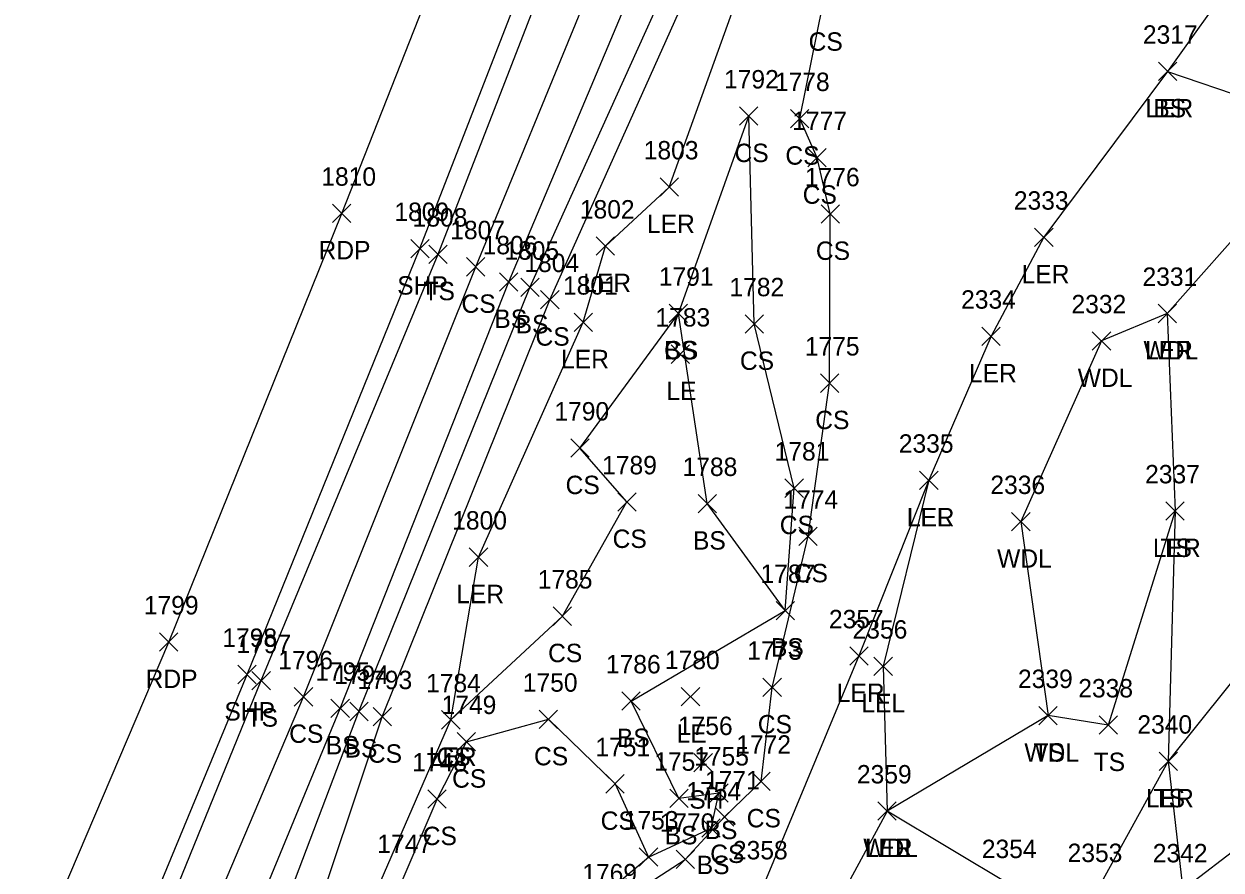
# Model space of a CAD drawing. Extents: x 1483143 to 1488182, y 802902 to 807581.
# Drawn here: x 1487782.5 to 1487912.6, y 806312.7 to 806404.6 of the extents above; entities that cross this region are included whole.
import ezdxf

# ---------------------------------------------------------------- set-up
doc = ezdxf.new("R2010")
doc.units = 0
for name, color, linetype in [('L_A', 7, 'Continuous'), ('L_I', 7, 'Continuous'), ('L_TIC', 7, 'Continuous'), ('LARO', 7, 'Continuous'), ('LAWA', 7, 'Continuous'), ('LELB', 7, 'Continuous'), ('P_A', 7, 'Continuous'), ('P_I', 7, 'Continuous'), ('P_TIC', 7, 'Continuous'), ('PET', 7, 'Continuous'), ('PSP', 7, 'Continuous')]:
    doc.layers.add(name, color=color, linetype=linetype)

msp = doc.modelspace()

# ---------------------------------------------------------------- linework, layer by layer
at = {"layer": 'L_TIC'}
for points in [[(1487905.78, 806398.47), (1487907.78, 806400.47)], [(1487907.78, 806398.47), (1487905.78, 806400.47)], [(1487905.78, 806398.47), (1487907.78, 806400.47)], [(1487907.78, 806398.47), (1487905.78, 806400.47)], [(1487860.27, 806393.61), (1487862.27, 806395.61)], [(1487862.27, 806393.61), (1487860.27, 806395.61)], [(1487860.27, 806393.61), (1487862.27, 806395.61)], [(1487862.27, 806393.61), (1487860.27, 806395.61)], [(1487865.81, 806393.33), (1487867.81, 806395.33)], [(1487867.81, 806393.33), (1487865.81, 806395.33)], [(1487867.69, 806389.08), (1487869.69, 806391.08)], [(1487869.69, 806389.08), (1487867.69, 806391.08)], [(1487851.63, 806385.9), (1487853.63, 806387.9)], [(1487853.63, 806385.9), (1487851.63, 806387.9)], [(1487869.12, 806382.98), (1487871.12, 806384.98)], [(1487871.12, 806382.98), (1487869.12, 806384.98)], [(1487892.33, 806380.44), (1487894.33, 806382.44)], [(1487894.33, 806380.44), (1487892.33, 806382.44)], [(1487826.52, 806378.6), (1487828.52, 806380.6)], [(1487828.52, 806378.6), (1487826.52, 806380.6)], [(1487844.69, 806379.48), (1487846.69, 806381.48)], [(1487846.69, 806379.48), (1487844.69, 806381.48)], [(1487830.61, 806377.23), (1487832.61, 806379.23)], [(1487832.61, 806377.23), (1487830.61, 806379.23)], [(1487834.19, 806375.59), (1487836.19, 806377.59)], [(1487836.19, 806375.59), (1487834.19, 806377.59)], [(1487836.5, 806375), (1487838.5, 806377)], [(1487838.5, 806375), (1487836.5, 806377)], [(1487838.66, 806373.66), (1487840.66, 806375.66)], [(1487840.66, 806373.66), (1487838.66, 806375.66)], [(1487852.63, 806372.17), (1487854.63, 806374.17)], [(1487854.63, 806372.17), (1487852.63, 806374.17)], [(1487852.63, 806372.17), (1487854.63, 806374.17)], [(1487854.63, 806372.17), (1487852.63, 806374.17)], [(1487905.74, 806372.16), (1487907.74, 806374.16)], [(1487907.74, 806372.16), (1487905.74, 806374.16)], [(1487905.74, 806372.16), (1487907.74, 806374.16)], [(1487907.74, 806372.16), (1487905.74, 806374.16)], [(1487842.29, 806371.21), (1487844.29, 806373.21)], [(1487844.29, 806371.21), (1487842.29, 806373.21)], [(1487860.87, 806371.03), (1487862.87, 806373.03)], [(1487862.87, 806371.03), (1487860.87, 806373.03)], [(1487886.6, 806369.68), (1487888.6, 806371.68)], [(1487888.6, 806369.68), (1487886.6, 806371.68)], [(1487898.59, 806369.18), (1487900.59, 806371.18)], [(1487900.59, 806369.18), (1487898.59, 806371.18)], [(1487852.83, 806367.74), (1487854.83, 806369.74)], [(1487854.83, 806367.74), (1487852.83, 806369.74)], [(1487869.05, 806364.59), (1487871.05, 806366.59)], [(1487871.05, 806364.59), (1487869.05, 806366.59)], [(1487841.93, 806357.53), (1487843.93, 806359.53)], [(1487843.93, 806357.53), (1487841.93, 806359.53)], [(1487879.83, 806354.03), (1487881.83, 806356.03)], [(1487881.83, 806354.03), (1487879.83, 806356.03)], [(1487879.83, 806354.03), (1487881.83, 806356.03)], [(1487881.83, 806354.03), (1487879.83, 806356.03)], [(1487865.2, 806353.18), (1487867.2, 806355.18)], [(1487867.2, 806353.18), (1487865.2, 806355.18)], [(1487847.04, 806351.68), (1487849.04, 806353.68)], [(1487849.04, 806351.68), (1487847.04, 806353.68)], [(1487855.77, 806351.5), (1487857.77, 806353.5)], [(1487857.77, 806351.5), (1487855.77, 806353.5)], [(1487906.59, 806350.7), (1487908.59, 806352.7)], [(1487908.59, 806350.7), (1487906.59, 806352.7)], [(1487906.59, 806350.7), (1487908.59, 806352.7)], [(1487908.59, 806350.7), (1487906.59, 806352.7)], [(1487889.83, 806349.54), (1487891.83, 806351.54)], [(1487891.83, 806349.54), (1487889.83, 806351.54)], [(1487866.72, 806347.95), (1487868.72, 806349.95)], [(1487868.72, 806347.95), (1487866.72, 806349.95)], [(1487830.91, 806345.68), (1487832.91, 806347.68)], [(1487832.91, 806345.68), (1487830.91, 806347.68)], [(1487864.24, 806339.88), (1487866.24, 806341.88)], [(1487866.24, 806339.88), (1487864.24, 806341.88)], [(1487840.03, 806339.27), (1487842.03, 806341.27)], [(1487842.03, 806339.27), (1487840.03, 806341.27)], [(1487872.24, 806334.95), (1487874.24, 806336.95)], [(1487874.24, 806334.95), (1487872.24, 806336.95)], [(1487874.87, 806333.83), (1487876.87, 806335.83)], [(1487876.87, 806333.83), (1487874.87, 806335.83)], [(1487807.3, 806332.26), (1487809.3, 806334.26)], [(1487809.3, 806332.26), (1487807.3, 806334.26)], [(1487811.9, 806330.5), (1487813.9, 806332.5)], [(1487813.9, 806330.5), (1487811.9, 806332.5)], [(1487853.94, 806330.51), (1487855.94, 806332.51)], [(1487855.94, 806330.51), (1487853.94, 806332.51)], [(1487862.81, 806331.53), (1487864.81, 806333.53)], [(1487864.81, 806331.53), (1487862.81, 806333.53)], [(1487815.88, 806329.25), (1487817.88, 806331.25)], [(1487817.88, 806329.25), (1487815.88, 806331.25)], [(1487847.49, 806330.05), (1487849.49, 806332.05)], [(1487849.49, 806330.05), (1487847.49, 806332.05)], [(1487817.92, 806328.91), (1487819.92, 806330.91)], [(1487819.92, 806328.91), (1487817.92, 806330.91)], [(1487820.45, 806328.34), (1487822.45, 806330.34)], [(1487822.45, 806328.34), (1487820.45, 806330.34)], [(1487827.9, 806328), (1487829.9, 806330)], [(1487829.9, 806328), (1487827.9, 806330)], [(1487827.9, 806328), (1487829.9, 806330)], [(1487829.9, 806328), (1487827.9, 806330)], [(1487838.5, 806328.06), (1487840.5, 806330.06)], [(1487840.5, 806328.06), (1487838.5, 806330.06)], [(1487892.79, 806328.46), (1487894.79, 806330.46)], [(1487894.79, 806328.46), (1487892.79, 806330.46)], [(1487892.79, 806328.46), (1487894.79, 806330.46)], [(1487894.79, 806328.46), (1487892.79, 806330.46)], [(1487899.33, 806327.44), (1487901.33, 806329.44)], [(1487901.33, 806327.44), (1487899.33, 806329.44)], [(1487829.6, 806325.63), (1487831.6, 806327.63)], [(1487831.6, 806325.63), (1487829.6, 806327.63)], [(1487855.32, 806323.35), (1487857.32, 806325.35)], [(1487857.32, 806323.35), (1487855.32, 806325.35)], [(1487905.84, 806323.5), (1487907.84, 806325.5)], [(1487907.84, 806323.5), (1487905.84, 806325.5)], [(1487905.84, 806323.5), (1487907.84, 806325.5)], [(1487907.84, 806323.5), (1487905.84, 806325.5)], [(1487861.61, 806321.32), (1487863.61, 806323.32)], [(1487863.61, 806321.32), (1487861.61, 806323.32)], [(1487845.74, 806321.05), (1487847.74, 806323.05)], [(1487847.74, 806321.05), (1487845.74, 806323.05)], [(1487857.03, 806320.04), (1487859.03, 806322.04)], [(1487859.03, 806320.04), (1487857.03, 806322.04)], [(1487826.41, 806319.39), (1487828.41, 806321.39)], [(1487828.41, 806319.39), (1487826.41, 806321.39)], [(1487852.69, 806319.47), (1487854.69, 806321.47)], [(1487854.69, 806319.47), (1487852.69, 806321.47)], [(1487857.64, 806317.45), (1487859.64, 806319.45)], [(1487859.64, 806317.45), (1487857.64, 806319.45)], [(1487875.29, 806318.09), (1487877.29, 806320.09)], [(1487877.29, 806318.09), (1487875.29, 806320.09)], [(1487875.29, 806318.09), (1487877.29, 806320.09)], [(1487877.29, 806318.09), (1487875.29, 806320.09)], [(1487875.29, 806318.09), (1487877.29, 806320.09)], [(1487877.29, 806318.09), (1487875.29, 806320.09)], [(1487856.18, 806316.24), (1487858.18, 806318.24)], [(1487858.18, 806316.24), (1487856.18, 806318.24)], [(1487849.38, 806313.09), (1487851.38, 806315.09)], [(1487851.38, 806313.09), (1487849.38, 806315.09)], [(1487849.38, 806313.09), (1487851.38, 806315.09)], [(1487851.38, 806313.09), (1487849.38, 806315.09)], [(1487853.37, 806312.84), (1487855.37, 806314.84)], [(1487855.37, 806312.84), (1487853.37, 806314.84)]]:
    msp.add_lwpolyline(points, dxfattribs=at)
at = {"layer": 'LARO'}
for points in [[(1487666.95, 805964.97), (1487680.31, 805984.75), (1487702.99, 806037.2), (1487715.7, 806058.03), (1487734.3, 806108.53), (1487742.02, 806134.63), (1487761.66, 806177.53), (1487786.65, 806227.9), (1487808.03, 806277.33), (1487813.76, 806294.17), (1487828.9, 806329), (1487831.91, 806346.68), (1487843.29, 806372.21), (1487845.69, 806380.48), (1487852.63, 806386.9), (1487863.18, 806416.3)], [(1487938.33, 806405.75), (1487927.08, 806402.62), (1487919.67, 806403.09), (1487914.11, 806409.79), (1487906.78, 806399.47), (1487893.33, 806381.44), (1487887.6, 806370.68), (1487880.83, 806355.03), (1487873.24, 806335.95), (1487862.81, 806310.84), (1487845.31, 806291.53), (1487837.06, 806275.13), (1487830.31, 806264.75), (1487822.51, 806259.14), (1487820.37, 806244.37)], [(1487906.74, 806373.16), (1487907.59, 806351.7), (1487906.84, 806324.5), (1487899.17, 806310.55), (1487889.85, 806310.98), (1487876.29, 806319.09)], [(1487880.83, 806355.03), (1487875.87, 806334.83), (1487876.29, 806319.09)]]:
    msp.add_lwpolyline(points, dxfattribs=at)
at = {"layer": 'LAWA'}
msp.add_lwpolyline([(1487942.37, 806424.18), (1487942.13, 806400.96), (1487924.66, 806393.36), (1487906.74, 806373.16), (1487899.59, 806370.18), (1487890.83, 806350.54), (1487893.79, 806329.46), (1487876.29, 806319.09), (1487863.09, 806294.65), (1487840.52, 806269.33), (1487843.55, 806264.22), (1487833.59, 806259.9), (1487830.72, 806250.51), (1487828.92, 806235.37), (1487823.44, 806218.85), (1487816.5, 806198.3), (1487812.31, 806191.59), (1487811.73, 806182.07)], dxfattribs=at)
at = {"layer": 'LELB'}
for points in [[(1487959.91, 806445.22), (1487960.75, 806398.74), (1487951.5, 806373.39), (1487932.63, 806356.69), (1487906.84, 806324.5), (1487908.42, 806310.52), (1487916.06, 806290.13), (1487905.83, 806276.22)], [(1487406.66, 805485.41), (1487431.45, 805531.24), (1487454.84, 805575.74), (1487473.75, 805612.05), (1487489.43, 805642.37), (1487507.64, 805678.53), (1487524.82, 805711.39), (1487541.86, 805746.09), (1487557.67, 805776.44), (1487575.49, 805812.01), (1487597.52, 805857.93), (1487620.62, 805906.82), (1487641.85, 805951.94), (1487662.18, 805996.35), (1487684.09, 806043.93), (1487694.42, 806066.95), (1487726.58, 806140.7), (1487745.85, 806185.55), (1487769.04, 806237.65), (1487788.58, 806284.85), (1487808.3, 806333.26), (1487827.52, 806379.6), (1487850.09, 806437.73)], [(1487410.04, 805483.24), (1487436.07, 805529.53), (1487459.78, 805575.03), (1487477.42, 805609.67), (1487492.45, 805639.09), (1487509.86, 805677.27), (1487528.68, 805708.85), (1487545.3, 805744.17), (1487561.79, 805774.32), (1487579.7, 805810.21), (1487602.04, 805856.31), (1487624.97, 805905.57), (1487645.72, 805950.02), (1487667.21, 805993.1), (1487687.16, 806043.23), (1487699.2, 806065.16), (1487730.65, 806138.87), (1487749.96, 806183.58), (1487772.93, 806235.17), (1487792.36, 806283.08), (1487812.9, 806331.5), (1487831.61, 806378.23), (1487855.61, 806436.65)], [(1487413.83, 805481.53), (1487440.22, 805526.89), (1487464.36, 805572.85), (1487481.71, 805606.55), (1487496.63, 805636.25), (1487514.9, 805673.97), (1487535.8, 805705.94), (1487549.07, 805741.59), (1487566.17, 805772.22), (1487583.99, 805807.69), (1487605.26, 805855.28), (1487629.33, 805903.01), (1487650.26, 805948.76), (1487670.48, 805991.25), (1487690.28, 806041.74), (1487702.22, 806061.37), (1487704.47, 806066.39), (1487735.28, 806136.71), (1487754, 806182.42), (1487776.55, 806233.47), (1487796.75, 806281.41), (1487816.88, 806330.25), (1487835.19, 806376.59), (1487859.78, 806434.97)], [(1487417, 805480.8), (1487442.28, 805525.8), (1487466.47, 805571.82), (1487483.84, 805604.86), (1487498.25, 805635.76), (1487518.24, 805671.86), (1487538.47, 805704.77), (1487552.2, 805739.67), (1487568.17, 805771.84), (1487585.97, 805806.76), (1487609.39, 805853.47), (1487632.34, 805900.81), (1487653.02, 805947.32), (1487672.59, 805990.01), (1487694.92, 806039.27), (1487707.45, 806059.25), (1487710.05, 806064.3), (1487737.97, 806135.43), (1487757.4, 806181.42), (1487778.76, 806231.94), (1487799.97, 806279.97), (1487818.92, 806329.91), (1487837.5, 806376), (1487863.45, 806433.38)], [(1487539.8, 805706.7), (1487554.99, 805738.51), (1487564.78, 805761.24), (1487572.42, 805770.06), (1487590.42, 805804.18), (1487613.31, 805851.36), (1487639.64, 805896.3), (1487657.07, 805945.9), (1487666.95, 805964.97), (1487675.89, 805987.99), (1487698.82, 806037.9), (1487713.56, 806059.8), (1487740.03, 806134.78), (1487759.8, 806179.98), (1487782.43, 806230.23), (1487804.48, 806278.55), (1487821.45, 806329.34), (1487839.66, 806374.66), (1487865.87, 806433.14)], [(1487966.07, 806415.18), (1487969.53, 806392.86), (1487952.94, 806357.28), (1487940.19, 806330.57), (1487921.69, 806320.66), (1487908.42, 806310.52), (1487904.09, 806299.8)], [(1487808.19, 806250.46), (1487814.65, 806254.45), (1487814.39, 806266.92), (1487820, 806278.4), (1487824.56, 806290.24), (1487835.69, 806296.25), (1487844.38, 806305.06), (1487845.93, 806308.34), (1487854.37, 806313.84), (1487858.64, 806318.45), (1487862.61, 806322.32), (1487863.81, 806332.53), (1487867.72, 806348.95), (1487870.05, 806365.59), (1487870.12, 806383.98), (1487868.69, 806390.08), (1487866.81, 806394.33), (1487869.32, 806406.71)], [(1487906.78, 806399.47), (1487924.66, 806393.36), (1487936.78, 806386.95), (1487951.5, 806373.39)], [(1487828.9, 806329), (1487841.03, 806340.27), (1487848.04, 806352.68), (1487842.93, 806358.53), (1487853.63, 806373.17), (1487861.27, 806394.61)], [(1487866.2, 806354.18), (1487861.87, 806372.03), (1487861.27, 806394.61)], [(1487813.76, 806294.17), (1487825.31, 806298.15), (1487840.36, 806305.67), (1487850.38, 806314.09), (1487857.18, 806317.24), (1487858.03, 806321.04), (1487853.69, 806320.47), (1487848.49, 806331.05), (1487865.24, 806340.88), (1487856.77, 806352.5), (1487853.63, 806373.17)], [(1487865.24, 806340.88), (1487866.2, 806354.18)], [(1487907.59, 806351.7), (1487900.33, 806328.44), (1487893.79, 806329.46)], [(1487825.31, 806298.15), (1487829.95, 806304.22), (1487823.6, 806311.52), (1487827.41, 806320.39), (1487830.6, 806326.63), (1487839.5, 806329.06), (1487846.74, 806322.05), (1487850.38, 806314.09)]]:
    msp.add_lwpolyline(points, dxfattribs=at)
at = {"layer": 'P_TIC'}
for points in [[(1487816.05, 806383.04), (1487818.05, 806385.04)], [(1487818.05, 806383.04), (1487816.05, 806385.04)], [(1487824.55, 806379.21), (1487826.55, 806381.21)], [(1487826.55, 806379.21), (1487824.55, 806381.21)], [(1487797.25, 806336.46), (1487799.25, 806338.46)], [(1487799.25, 806336.46), (1487797.25, 806338.46)], [(1487805.77, 806332.93), (1487807.77, 806334.93)], [(1487807.77, 806332.93), (1487805.77, 806334.93)]]:
    msp.add_lwpolyline(points, dxfattribs=at)
at = {"layer": 'PET'}
msp.add_lwpolyline([(1487396.33, 805490.41), (1487421.9, 805537.94), (1487444.13, 805580.16), (1487464.29, 805618.83), (1487479.8, 805648.39), (1487498.08, 805684.27), (1487514.57, 805717.15), (1487530.55, 805749.06), (1487547.16, 805782.47), (1487564.33, 805817.54), (1487585.71, 805863.32), (1487608.89, 805911.38), (1487630.35, 805956.68), (1487651.22, 806001.25), (1487672.63, 806048.33), (1487683.65, 806072.29), (1487715.61, 806144.47), (1487735.35, 806190.47), (1487757.48, 806241.03), (1487777.65, 806289.15), (1487798.25, 806337.46), (1487817.05, 806384.04), (1487839.67, 806441.4)], dxfattribs=at)
at = {"layer": 'PSP'}
msp.add_lwpolyline([(1487405.03, 805486.21), (1487429.8, 805532.42), (1487452.92, 805576.31), (1487472.37, 805613.24), (1487487.86, 805643.29), (1487506.35, 805679.4), (1487523.34, 805712.45), (1487540.38, 805746.64), (1487556.03, 805777.85), (1487573.44, 805813.27), (1487595.34, 805859.04), (1487618.37, 805906.67), (1487640.09, 805952.42), (1487660.18, 805997.21), (1487682.38, 806044.71), (1487693.04, 806068.56), (1487725.12, 806141.19), (1487744.39, 806185.87), (1487766.81, 806238.55), (1487786.8, 806285.64), (1487806.77, 806333.93), (1487825.55, 806380.21), (1487847.81, 806437.56)], dxfattribs=at)

# ---------------------------------------------------------------- texts
at = {"layer": 'L_A'}
for s, p in [('CS', (1487867.77, 806401.71)), ('LER', (1487904.36, 806394.47)), ('BS', (1487905.22, 806394.47)), ('CS', (1487859.72, 806389.61)), ('CS', (1487859.72, 806389.61)), ('CS', (1487865.25, 806389.33)), ('CS', (1487867.13, 806385.08)), ('LER', (1487850.21, 806381.9)), ('CS', (1487868.56, 806378.98)), ('LER', (1487890.91, 806376.44)), ('TS', (1487825.93, 806374.6)), ('LER', (1487843.28, 806375.48)), ('CS', (1487830.06, 806373.23)), ('BS', (1487833.63, 806371.59)), ('BS', (1487835.94, 806371)), ('CS', (1487838.1, 806369.66)), ('CS', (1487852.07, 806368.17)), ('BS', (1487852.07, 806368.17)), ('WDL', (1487904.16, 806368.16)), ('LER', (1487904.33, 806368.16)), ('LER', (1487840.88, 806367.21)), ('CS', (1487860.31, 806367.03)), ('LER', (1487885.19, 806365.68)), ('WDL', (1487897.01, 806365.18)), ('LE', (1487852.32, 806363.74)), ('CS', (1487868.49, 806360.59)), ('CS', (1487841.37, 806353.53)), ('LER', (1487878.41, 806350.03)), ('LEL', (1487878.46, 806350.03)), ('CS', (1487864.64, 806349.18)), ('CS', (1487846.48, 806347.68)), ('BS', (1487855.21, 806347.5)), ('LER', (1487905.17, 806346.7)), ('TS', (1487906, 806346.7)), ('WDL', (1487888.25, 806345.54)), ('CS', (1487866.16, 806343.95)), ('LER', (1487829.49, 806341.68)), ('BS', (1487863.68, 806335.88)), ('CS', (1487839.47, 806335.27)), ('LER', (1487870.83, 806330.95)), ('LEL', (1487873.5, 806329.83)), ('TS', (1487806.71, 806328.26)), ('CS', (1487811.34, 806326.5)), ('LE', (1487853.43, 806326.51)), ('CS', (1487862.25, 806327.53)), ('BS', (1487815.32, 806325.25)), ('BS', (1487846.94, 806326.05)), ('BS', (1487817.36, 806324.91)), ('CS', (1487819.89, 806324.34)), ('LER', (1487826.49, 806324)), ('CS', (1487827.34, 806324)), ('CS', (1487837.94, 806324.06)), ('WDL', (1487891.21, 806324.46)), ('TS', (1487892.2, 806324.46)), ('TS', (1487898.74, 806323.44)), ('CS', (1487829.04, 806321.63)), ('SH', (1487854.81, 806319.35)), ('LER', (1487904.42, 806319.5)), ('TS', (1487905.25, 806319.5)), ('CS', (1487845.18, 806317.05)), ('BS', (1487856.47, 806316.04)), ('CS', (1487861.05, 806317.32)), ('CS', (1487825.85, 806315.39)), ('BS', (1487852.13, 806315.47)), ('CS', (1487857.08, 806313.45)), ('WDL', (1487873.71, 806314.09)), ('LER', (1487873.87, 806314.09)), ('LEL', (1487873.93, 806314.09)), ('BS', (1487855.62, 806312.24))]:
    msp.add_text(s, height=2, dxfattribs=at).set_placement(p)
at = {"layer": 'L_I'}
for s, p in [('2317', (1487904.09, 806402.47)), ('2317', (1487904.09, 806402.47)), ('1792', (1487858.58, 806397.61)), ('1792', (1487858.58, 806397.61)), ('1778', (1487864.11, 806397.33)), ('1777', (1487865.99, 806393.08)), ('1803', (1487849.86, 806389.9)), ('1776', (1487867.37, 806386.98)), ('2333', (1487890.07, 806384.44)), ('1808', (1487824.75, 806382.6)), ('1802', (1487842.92, 806383.48)), ('1807', (1487828.84, 806381.23)), ('1806', (1487832.36, 806379.59)), ('1805', (1487834.72, 806379)), ('1804', (1487836.89, 806377.66)), ('1791', (1487851.5, 806376.17)), ('1791', (1487851.5, 806376.17)), ('2331', (1487904.05, 806376.16)), ('2331', (1487904.05, 806376.16)), ('1801', (1487841.09, 806375.21)), ('1782', (1487859.17, 806375.03)), ('2334', (1487884.34, 806373.68)), ('2332', (1487896.33, 806373.18)), ('1783', (1487851.13, 806371.74)), ('1775', (1487867.36, 806368.59)), ('1790', (1487840.15, 806361.53)), ('2335', (1487877.57, 806358.03)), ('2335', (1487877.57, 806358.03)), ('1781', (1487864.08, 806357.18)), ('1789', (1487845.34, 806355.68)), ('1788', (1487854.08, 806355.5)), ('2337', (1487904.33, 806354.7)), ('2337', (1487904.33, 806354.7)), ('2336', (1487887.52, 806353.54)), ('1774', (1487865.03, 806351.95)), ('1800', (1487829.05, 806349.68)), ('1787', (1487862.55, 806343.88)), ('1785', (1487838.34, 806343.27)), ('2357', (1487869.98, 806338.95)), ('2356', (1487872.55, 806337.83)), ('1797', (1487805.61, 806336.26)), ('1796', (1487810.15, 806334.5)), ('1780', (1487852.16, 806334.51)), ('1773', (1487861.11, 806335.53)), ('1795', (1487814.18, 806333.25)), ('1786', (1487845.75, 806334.05)), ('1794', (1487816.22, 806332.91)), ('1793', (1487818.76, 806332.34)), ('1784', (1487826.21, 806332)), ('1784', (1487826.21, 806332)), ('1750', (1487836.72, 806332.06)), ('2339', (1487890.52, 806332.46)), ('2339', (1487890.52, 806332.46)), ('2338', (1487897.07, 806331.44)), ('1749', (1487827.9, 806329.63)), ('1756', (1487853.57, 806327.35)), ('2340', (1487903.49, 806327.5)), ('2340', (1487903.49, 806327.5)), ('1772', (1487859.91, 806325.32)), ('1751', (1487844.61, 806325.05)), ('1755', (1487855.34, 806324.04)), ('1748', (1487824.71, 806323.39)), ('1757', (1487851, 806323.47)), ('1771', (1487856.51, 806321.45)), ('2359', (1487873.02, 806322.09)), ('2359', (1487873.02, 806322.09)), ('2359', (1487873.02, 806322.09)), ('1754', (1487854.48, 806320.24)), ('1753', (1487847.69, 806317.09)), ('1753', (1487847.69, 806317.09)), ('1770', (1487851.59, 806316.84)), ('1747', (1487820.91, 806314.52)), ('2358', (1487859.55, 806313.84)), ('2358', (1487859.55, 806313.84)), ('2354', (1487886.59, 806313.98)), ('2353', (1487895.91, 806313.55)), ('2342', (1487905.16, 806313.52)), ('2342', (1487905.16, 806313.52)), ('1769', (1487843.18, 806311.34))]:
    msp.add_text(s, height=2, dxfattribs=at).set_placement(p)
at = {"layer": 'P_A'}
for s, p in [('RDP', (1487814.53, 806379.04)), ('SHP', (1487823.08, 806375.21)), ('RDP', (1487795.74, 806332.46)), ('SHP', (1487804.3, 806328.93))]:
    msp.add_text(s, height=2, dxfattribs=at).set_placement(p)
at = {"layer": 'P_I'}
for s, p in [('1810', (1487814.83, 806387.04)), ('1809', (1487822.77, 806383.21)), ('1799', (1487795.55, 806340.46)), ('1798', (1487804.08, 806336.93))]:
    msp.add_text(s, height=2, dxfattribs=at).set_placement(p)

doc.saveas('drawing.dxf')
